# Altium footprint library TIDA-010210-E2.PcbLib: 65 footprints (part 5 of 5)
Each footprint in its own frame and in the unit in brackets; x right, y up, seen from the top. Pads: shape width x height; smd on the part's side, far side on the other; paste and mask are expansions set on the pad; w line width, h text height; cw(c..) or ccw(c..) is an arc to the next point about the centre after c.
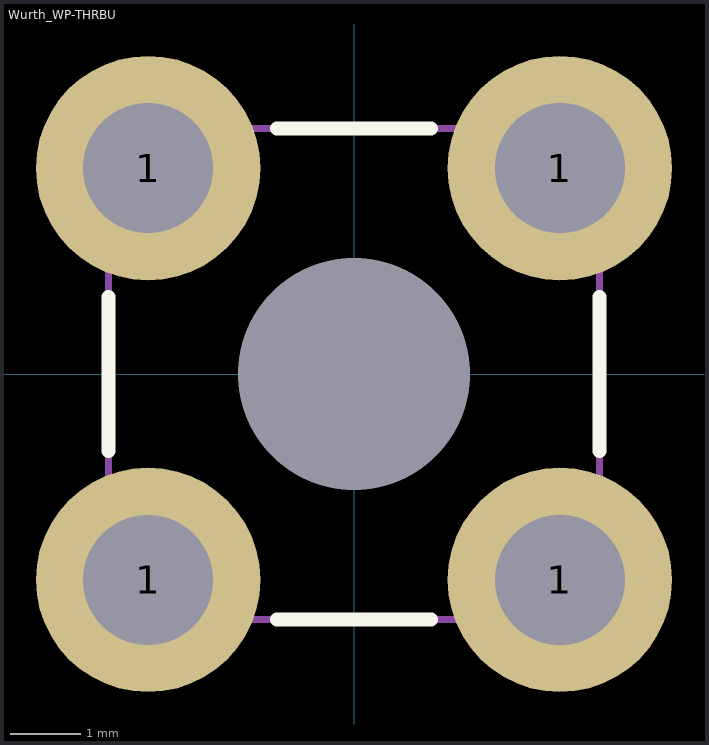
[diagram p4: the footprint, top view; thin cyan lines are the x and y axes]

## Wurth_WP-THRBU [mm] "Power Element Bush, M3, TH"
height 3
pads (9):
  round 3.2 hole 1.85: 1(-2.935,-2.935) 1(-2.935,2.935) 1(2.935,-2.935) 1(2.935,2.935)
  round 3.1 on Top Paste: ""(-2.935,-2.935) ""(-2.935,2.935) ""(2.935,-2.935) ""(2.935,2.935)
  round 3 hole 3.3 unplated mask+0.102: ""(0,0)
Top Overlay:
  lines w0.2: -3.5,-1.1 -3.5,1.1 ; -1.1,-3.5 1.1,-3.5 ; -1.1,3.5 1.1,3.5 ; 3.5,-1.1 3.5,1.1
Mechanical 5:
  lines w0.1: -3.5,-3.5 -3.5,3.5 3.5,3.5 3.5,-3.5 -3.5,-3.5
  text ".Designator" at -2.2,-0.5 h1.3
3D body "74650073R.stp": height 3, standoff -2.5, extent -3.5,-3.5 3.5,3.5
